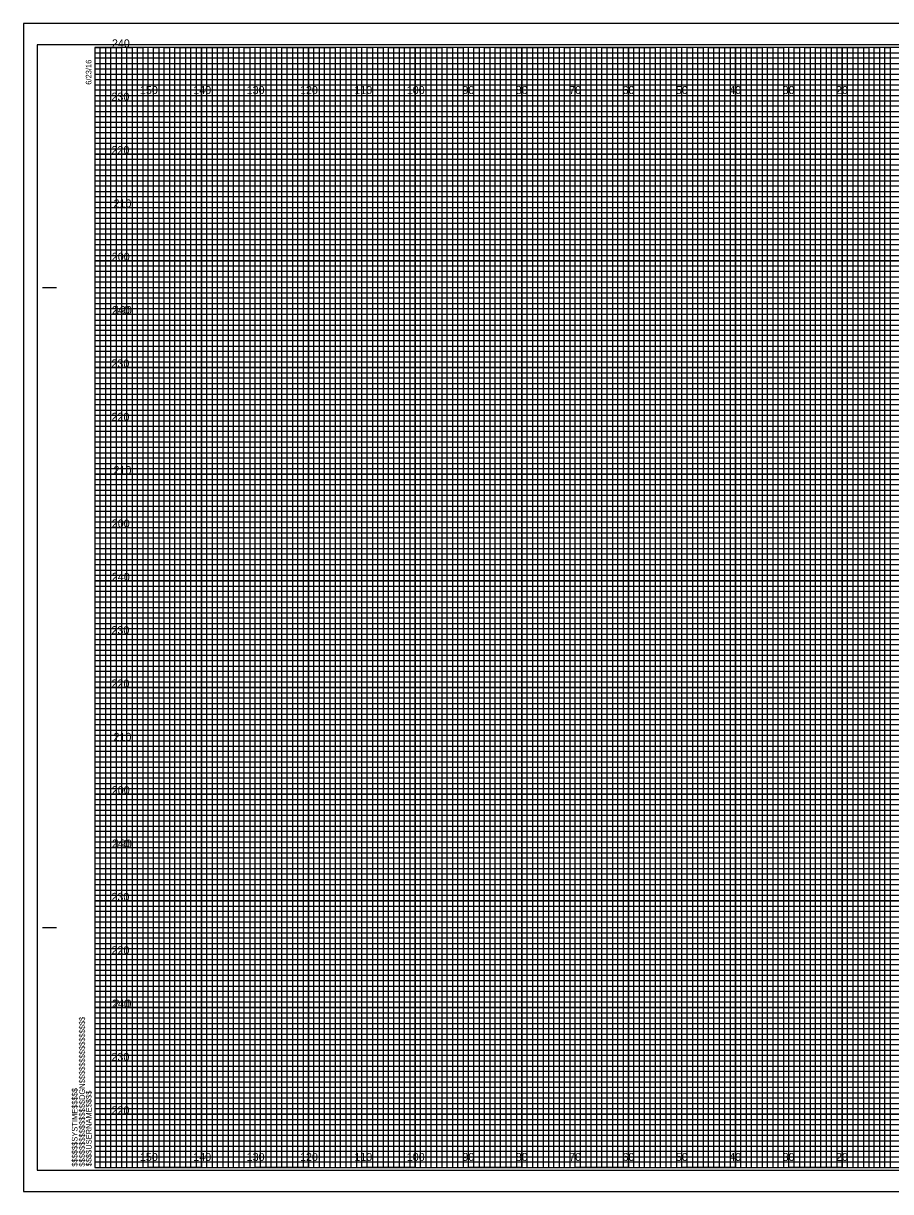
# Model space of a CAD drawing. Extents: x -13 to 359, y -5 to 2854.
# Drawn here: x -13.4 to 149.1, y 1315.5 to 1534.5 of the extents above; entities that cross this region are included whole.
import ezdxf

# ---------------------------------------------------------------- set-up
doc = ezdxf.new("R2010")
doc.units = 0
for name, color, linetype in [('Exist Cross Section Cell', 7, 'Continuous'), ('Exist XS Ground Line', 7, 'Continuous'), ('Prop CMT Concrete Structures', 7, 'Continuous'), ('Prop CMT DNC', 7, 'Continuous'), ('Prop CMT Pvmt Course 1', 7, 'Continuous'), ('Prop CMT Pvmt Course 1 CG', 7, 'Continuous'), ('Prop CMT Pvmt Course 2', 7, 'Continuous'), ('Prop CMT Shear Line', 7, 'Continuous'), ('Prop CMT Slope Grass', 7, 'Continuous'), ('Prop CMT Subgrade Earthwork', 7, 'Continuous'), ('Scratch_Level_0', 7, 'Continuous')]:
    doc.layers.add(name, color=color, linetype=linetype)

msp = doc.modelspace()

# ---------------------------------------------------------------- linework, layer by layer
at = {"layer": 'Exist XS Ground Line'}
for p, q in [((10, 1530), (0, 1530)), ((10, 1320), (10, 1530)), ((30, 1530), (20, 1530)), ((20, 1530), (20, 1320)), ((30, 1320), (30, 1530)), ((50, 1530), (40, 1530)), ((40, 1530), (40, 1320)), ((50, 1320), (50, 1530)), ((70, 1530), (60, 1530)), ((60, 1530), (60, 1320)), ((70, 1320), (70, 1530)), ((90, 1530), (80, 1530)), ((80, 1530), (80, 1320)), ((90, 1320), (90, 1530)), ((110, 1530), (100, 1530)), ((100, 1530), (100, 1320)), ((110, 1320), (110, 1530)), ((130, 1530), (120, 1530)), ((120, 1530), (120, 1320)), ((130, 1320), (130, 1530)), ((150, 1530), (140, 1530)), ((140, 1530), (140, 1320)), ((20, 1320), (10, 1320)), ((40, 1320), (30, 1320)), ((60, 1320), (50, 1320)), ((80, 1320), (70, 1320)), ((100, 1320), (90, 1320)), ((120, 1320), (110, 1320)), ((140, 1320), (130, 1320))]:
    msp.add_line(p, q, dxfattribs=at)
for points in [[(0, 1520), (320, 1520), (320, 1510), (0, 1510)], [(0, 1500), (320, 1500), (320, 1490), (0, 1490)], [(0, 1480), (320, 1480), (320, 1470), (0, 1470)], [(0, 1460), (320, 1460), (320, 1450), (0, 1450)], [(0, 1440), (320, 1440), (320, 1430), (0, 1430)], [(0, 1420), (320, 1420), (320, 1410), (0, 1410)], [(0, 1400), (320, 1400), (320, 1390), (0, 1390)], [(0, 1380), (320, 1380), (320, 1370), (0, 1370)], [(0, 1360), (320, 1360), (320, 1350), (0, 1350)], [(0, 1340), (320, 1340), (320, 1330), (0, 1330)]]:
    msp.add_lwpolyline(points, dxfattribs=at)
at = {"layer": 'Prop CMT Concrete Structures'}
for p, q in [((-9.8, 1485), (-7.3, 1485)), ((-9.7, 1485), (-7.2, 1485)), ((-9.8, 1365), (-7.3, 1365)), ((-9.7, 1365), (-7.2, 1365)), ((0, 1320), (0, 1320)), ((0, 1320), (0, 1320)), ((0, 1320), (0, 1320)), ((0, 1320), (0, 1320)), ((0, 1320), (0, 1320)), ((0, 1320), (0, 1320)), ((0, 1320), (0, 1320))]:
    msp.add_line(p, q, dxfattribs=at)
msp.add_lwpolyline([(320, 1530), (0, 1530), (0, 1320), (320, 1320)], close=True, dxfattribs=at)
at = {"layer": 'Prop CMT DNC'}
for p, q in [((323.3, 1534.5), (-13.4, 1534.5)), ((-13.4, 1534.5), (-13.4, 1315.5)), ((-13.4, 1315.5), (323.3, 1315.5))]:
    msp.add_line(p, q, dxfattribs=at)
at = {"layer": 'Prop CMT Pvmt Course 1'}
for p, q in [((0, 1529), (260, 1529)), ((260, 1527.98), (0, 1527.98)), ((0, 1527.98), (0, 1527)), ((0, 1527), (260, 1527)), ((260, 1525.89), (0, 1525.89)), ((0, 1525.89), (0, 1524)), ((0, 1524), (320, 1524))]:
    msp.add_line(p, q, dxfattribs=at)
for points in [[(0, 1523), (270, 1523), (320, 1523), (320, 1522), (0, 1522)], [(0, 1521), (320, 1521), (320, 1519), (0, 1519)], [(0, 1518), (320, 1518), (320, 1517), (0, 1516.98)], [(0, 1516), (320, 1516), (320, 1514), (0, 1514)], [(0, 1513), (320, 1513), (320, 1512), (0, 1512)], [(0, 1511), (320, 1511), (320, 1509), (0, 1509)], [(0, 1508), (320, 1508), (320, 1507), (0, 1507)], [(0, 1506), (320, 1506), (320, 1504), (0, 1504)], [(0, 1503), (320, 1503), (320, 1502), (0, 1502)], [(0, 1501), (320, 1501), (320, 1499), (0, 1499)], [(0, 1498), (320, 1498), (320, 1497), (0, 1497)], [(0, 1496), (320, 1496), (320, 1493.95), (320, 1493), (320, 1492), (0, 1492)], [(0, 1494), (320, 1494), (320, 1493), (0, 1493)], [(0, 1491), (320, 1491), (320, 1489), (0, 1489.03)], [(0, 1489.03), (320, 1489), (320, 1488), (0, 1488)], [(0, 1487), (320, 1487), (320, 1486), (0, 1486)], [(0, 1484), (320, 1484), (320, 1483), (0, 1483)], [(0, 1482), (320, 1482), (320, 1481), (0, 1481)], [(-0.07, 1478.89), (320, 1478.89), (320, 1477.88), (-0.07, 1477.88)], [(0, 1477), (320, 1477), (320, 1476), (0, 1476)], [(0, 1474), (320, 1474), (320, 1473), (0, 1473)], [(0, 1472), (320, 1472), (320, 1471), (0, 1471)], [(0, 1469), (320, 1469), (320, 1468), (0, 1468)], [(0, 1467), (320, 1467), (320, 1466), (0, 1466)], [(0, 1464), (320, 1464), (320, 1463), (0, 1463)], [(0, 1462), (320, 1462), (320, 1461), (0, 1461)], [(0, 1459), (320, 1459), (319.99, 1457.98), (0, 1458)], [(0, 1457), (320, 1457), (320, 1456), (0, 1456)], [(0, 1454), (320, 1454), (320, 1453), (0, 1453)], [(0, 1452), (320, 1452), (320, 1451), (0, 1451)], [(0, 1449), (320, 1449), (320, 1448), (0, 1448)], [(0, 1447), (320, 1447), (320, 1446), (0, 1446)], [(0, 1444), (320, 1444), (320, 1443), (0, 1443)], [(0, 1442), (320, 1442), (320, 1441), (0, 1441)], [(0, 1439), (320, 1439), (320, 1438), (0, 1438)], [(0, 1436.99), (320.07, 1436.91), (320, 1436), (0, 1436)], [(0, 1434), (320, 1434), (320, 1433), (0, 1433)], [(0, 1432), (320, 1432), (320, 1431), (0, 1431)], [(0, 1429), (320, 1429), (320, 1428), (0, 1428)], [(0, 1427), (320, 1427), (320, 1426), (0, 1426)], [(0, 1424), (320, 1424), (320, 1423), (0, 1423)], [(0, 1422), (320, 1422), (320, 1421), (0, 1421)], [(0, 1419), (320, 1419), (320, 1418), (0, 1418)], [(0, 1417), (320, 1417), (320, 1416), (0, 1416)], [(0, 1414), (320, 1414), (320, 1413), (0, 1413)], [(0, 1412), (320, 1412), (320, 1411), (0, 1411)], [(0, 1409), (320, 1409), (320, 1408), (0, 1408)], [(0, 1407), (320, 1407), (320, 1406), (0, 1406)], [(0, 1404), (320, 1404), (320, 1403), (0, 1403)], [(0, 1402), (320, 1402), (320, 1401), (0, 1401)], [(0, 1399), (320, 1399), (319.99, 1397.98), (0, 1398)], [(0, 1397), (320, 1397), (320, 1396), (0, 1396)], [(0, 1394), (320, 1394), (320, 1393), (0, 1393)], [(0, 1392), (320, 1392), (320, 1391), (0, 1391)], [(0, 1389), (320, 1389), (320, 1388), (0, 1388)], [(0, 1387), (320, 1387), (320, 1386), (0, 1386)], [(0, 1384), (320, 1384), (320, 1383), (0, 1383)], [(0, 1382), (320, 1382), (320, 1381), (0, 1381)], [(0, 1379), (320, 1379), (320, 1378), (0, 1378)], [(0, 1376.99), (320.07, 1376.91), (320, 1376), (0, 1376)], [(0, 1374), (320, 1374), (320, 1373), (0, 1373)], [(0, 1372), (320, 1372), (320, 1371), (0, 1371)], [(0, 1369), (320, 1369), (320, 1368), (0, 1368)], [(0, 1367), (320, 1367), (320, 1366), (0, 1366)], [(0, 1364), (320, 1364), (320, 1363), (0, 1363)], [(0, 1362), (320, 1362), (320, 1361), (0, 1361)], [(0, 1359), (320, 1359), (320, 1358), (0, 1358)], [(0, 1357), (320, 1357), (320, 1356), (0, 1356)], [(0, 1354), (320, 1354), (320, 1353), (0, 1353)], [(0, 1352), (320, 1352), (320, 1351), (0, 1351)], [(0, 1349), (320, 1349), (320, 1348), (0, 1348)], [(0, 1347), (320, 1347), (320, 1346), (0, 1346)], [(0, 1344), (320, 1344), (320, 1343), (0, 1343)], [(0, 1342), (320, 1342), (320, 1341), (0, 1341)], [(0, 1339), (320, 1339), (320, 1338), (0, 1338)], [(0, 1337), (320, 1337), (320, 1336), (0, 1336)], [(0, 1334), (320, 1334), (320, 1333), (0, 1333)], [(0, 1332), (320, 1332), (320, 1331), (0, 1331)], [(0, 1329), (320, 1329), (320, 1328), (0, 1328)], [(0, 1327), (320, 1327), (320, 1326), (0, 1326)], [(0, 1324), (320, 1324), (320, 1323), (0, 1323)], [(0, 1322), (320, 1322), (320, 1321), (0, 1321)]]:
    msp.add_lwpolyline(points, dxfattribs=at)
at = {"layer": 'Prop CMT Pvmt Course 1 CG'}
for points in [[(0, 1320), (1, 1320), (1, 1530), (2, 1530), (2, 1320)], [(2, 1320), (3, 1320), (3, 1530), (4, 1530), (4, 1320)], [(5, 1320), (6, 1320), (6, 1530), (7, 1530), (7, 1320)], [(7, 1320), (8, 1320), (8, 1530), (9, 1530), (9, 1320)], [(10, 1320), (11, 1320), (11, 1530), (12, 1530), (12, 1320)], [(12, 1320), (13, 1320), (13, 1530), (14, 1530), (14, 1320)], [(15, 1320), (16, 1320), (16, 1530), (17, 1530), (17, 1320)], [(17, 1320), (18, 1320), (18, 1530), (19, 1530), (19, 1320)], [(20, 1320), (21, 1320), (21, 1530), (22, 1530), (22, 1320)], [(22, 1320), (23, 1320), (23, 1530), (24, 1530), (24, 1320)], [(25, 1320), (26, 1320), (26, 1530), (27, 1530), (27, 1320)], [(27, 1320), (28, 1320), (28, 1530), (29, 1530), (29, 1320)], [(30, 1320), (31, 1320), (31, 1530), (32, 1530), (32, 1320)], [(32, 1320), (33, 1320), (33, 1530), (34, 1530), (34, 1320)], [(35, 1320), (36, 1320), (36, 1530), (37, 1530), (37, 1320)], [(37, 1320), (38, 1320), (38, 1530), (39, 1530), (39, 1320)], [(40, 1320), (41, 1320), (41, 1530), (42, 1530), (42, 1320)], [(42, 1320), (43, 1320), (43, 1530), (44, 1530), (44, 1320)], [(45, 1320), (46, 1320), (46, 1530), (47, 1530), (47, 1320)], [(47, 1320), (48, 1320), (48, 1530), (49, 1530), (49, 1320)], [(50, 1320), (51, 1320), (51, 1530), (52, 1530), (52, 1320)], [(52, 1320), (53, 1320), (53, 1530), (54, 1530), (54, 1320)], [(55, 1320), (56, 1320), (56, 1530), (57, 1530), (57, 1320)], [(57, 1320), (58, 1320), (58, 1530), (59, 1530), (59, 1320)], [(60, 1320), (61, 1320), (61, 1530), (62, 1530), (62, 1320)], [(62, 1320), (63, 1320), (63, 1530), (64, 1530), (64, 1320)], [(65, 1320), (66, 1320), (66, 1530), (67, 1530), (67, 1320)], [(67, 1320), (68, 1320), (68, 1530), (69, 1530), (69, 1320)], [(70, 1320), (71, 1320), (71, 1530), (72, 1530), (72, 1320)], [(72, 1320), (73, 1320), (73, 1530), (74, 1530), (74, 1320)], [(75, 1320), (76, 1320), (76, 1530), (77, 1530), (77, 1320)], [(77, 1320), (78, 1320), (78, 1530), (79, 1530), (79, 1320)], [(80, 1320), (81, 1320), (81, 1530), (82, 1530), (82, 1320)], [(82, 1320), (83, 1320), (83, 1530), (84, 1530), (84, 1320)], [(85, 1320), (86, 1320), (86, 1530), (87, 1530), (87, 1320)], [(87, 1320), (88, 1320), (88, 1530), (89, 1530), (89, 1320)], [(90, 1320), (91, 1320), (91, 1530), (92, 1530), (92, 1320)], [(92, 1320), (93, 1320), (93, 1530), (94, 1530), (94, 1320)], [(95, 1320), (96, 1320), (96, 1530), (97, 1530), (97, 1320)], [(97, 1320), (98, 1320), (98, 1530), (99, 1530), (99, 1320)], [(100, 1320), (101, 1320), (101, 1530), (102, 1530), (102, 1320)], [(102, 1320), (103, 1320), (103, 1530), (104, 1530), (104, 1320)], [(105, 1320), (106, 1320), (106, 1530), (107, 1530), (107, 1320)], [(107, 1320), (108, 1320), (108, 1530), (109, 1530), (109, 1320)], [(110, 1320), (111, 1320), (111, 1530), (112, 1530), (112, 1320)], [(112, 1320), (113, 1320), (113, 1530), (114, 1530), (114, 1320)], [(115, 1320), (116, 1320), (116, 1530), (117, 1530), (117, 1320)], [(117, 1320), (118, 1320), (118, 1530), (119, 1530), (119, 1320)], [(120, 1320), (121, 1320), (121, 1530), (122, 1530), (122, 1320)], [(122, 1320), (123, 1320), (123, 1530), (124, 1530), (124, 1320)], [(125, 1320), (126, 1320), (126, 1530), (127, 1530), (127, 1320)], [(127, 1320), (128, 1320), (128, 1530), (129, 1530), (129, 1320)], [(130, 1320), (131, 1320), (131, 1530), (132, 1530), (132, 1320)], [(132, 1320), (133, 1320), (133, 1530), (134, 1530), (134, 1320)], [(135, 1320), (136, 1320), (136, 1530), (137, 1530), (137, 1320)], [(137, 1320), (138, 1320), (138, 1530), (139, 1530), (139, 1320)], [(140, 1320), (141, 1320), (141, 1530), (142, 1530), (142, 1320)], [(142, 1320), (143, 1320), (143, 1530), (144, 1530), (144, 1320)], [(145, 1320), (146, 1320), (146, 1530), (147, 1530), (147, 1320)], [(147, 1320), (148, 1320), (148, 1530), (149, 1530), (149, 1320)]]:
    msp.add_lwpolyline(points, dxfattribs=at)
at = {"layer": 'Prop CMT Shear Line'}
for p, q in [((10, 1320), (10, 1530)), ((20, 1320), (20, 1530)), ((30, 1320), (30, 1530)), ((40, 1320), (40, 1530)), ((50, 1320), (50, 1530)), ((60, 1320), (60, 1530)), ((70, 1320), (70, 1530)), ((80, 1320), (80, 1530)), ((90, 1320), (90, 1530)), ((100, 1320), (100, 1530)), ((110, 1320), (110, 1530)), ((120, 1320), (120, 1530)), ((130, 1320), (130, 1530)), ((140, 1320), (140, 1530)), ((0, 1520), (320, 1520)), ((0, 1510), (320, 1510)), ((0, 1500), (320, 1500)), ((0, 1490), (320, 1490)), ((0, 1480), (320, 1480)), ((0, 1470), (320, 1470)), ((0, 1460), (320, 1460)), ((0, 1450), (320, 1450)), ((0, 1440), (320, 1440)), ((0, 1430), (320, 1430)), ((0, 1420), (320, 1420)), ((0, 1410), (320, 1410)), ((0, 1400), (320, 1400)), ((0, 1390), (320, 1390)), ((0, 1380), (320, 1380)), ((0, 1370), (320, 1370)), ((0, 1360), (320, 1360)), ((0, 1350), (320, 1350)), ((0, 1340), (320, 1340)), ((0, 1330), (320, 1330))]:
    msp.add_line(p, q, dxfattribs=at)
at = {"layer": 'Prop CMT Slope Grass'}
msp.add_lwpolyline([(-10.8, 1319.5), (322.4, 1319.5), (322.4, 1530.5), (-10.8, 1530.5)], close=True, dxfattribs=at)
at = {"layer": 'Prop CMT Subgrade Earthwork'}
msp.add_lwpolyline([(-13.4, 1315.5), (323.3, 1315.5), (323.3, 1534.5), (-13.4, 1534.5)], close=True, dxfattribs=at)
at = {"layer": 'Scratch_Level_0'}
for points in [[(0, 1530), (5, 1530), (5, 1320), (15, 1320), (15, 1530), (25, 1530), (25, 1320), (35, 1320), (35, 1530), (45, 1530), (45, 1320), (55, 1320), (55, 1530), (65, 1530), (65, 1320), (75, 1320), (75, 1530), (85, 1530), (85, 1320), (95, 1320), (95, 1530), (105, 1530), (105, 1320), (115, 1320), (115, 1530), (125, 1530), (125, 1320), (135, 1320), (135, 1530), (145, 1530), (145, 1320), (155, 1320)], [(0, 1525), (275, 1525)], [(0, 1505), (320, 1505), (320, 1515), (0, 1515)], [(0, 1485), (320, 1485), (320, 1495), (0, 1495)], [(0, 1465), (320, 1465), (320, 1475), (0, 1475)], [(0, 1445), (320, 1445), (320, 1455), (0, 1455)], [(0, 1425), (320, 1425), (320, 1435), (0, 1435)], [(0, 1405), (320, 1405), (320, 1415), (0, 1415)], [(0, 1385), (320, 1385), (320, 1395), (0, 1395)], [(0, 1365), (320, 1365), (320, 1375), (0, 1375)], [(0, 1345), (320, 1345), (320, 1355), (0, 1355)], [(0, 1325), (320, 1325), (320, 1335), (0, 1335)]]:
    msp.add_lwpolyline(points, dxfattribs=at)

# ---------------------------------------------------------------- texts
at = {"layer": 'Exist Cross Section Cell'}
for s, p in [('150', (8.44, 1521.25)), ('140', (18.44, 1521.25)), ('130', (28.44, 1521.25)), ('120', (38.44, 1521.25)), ('110', (48.62, 1521.25)), ('100', (58.44, 1521.25)), ('90', (68.86, 1521.25)), ('80', (78.86, 1521.25)), ('70', (88.86, 1521.25)), ('60', (98.86, 1521.25)), ('50', (108.86, 1521.25)), ('40', (118.86, 1521.25)), ('30', (128.86, 1521.25)), ('20', (138.86, 1521.25)), ('150', (8.44, 1321.25)), ('140', (18.44, 1321.25)), ('130', (28.44, 1321.25)), ('120', (38.44, 1321.25)), ('110', (48.62, 1321.25)), ('100', (58.44, 1321.25)), ('90', (68.86, 1321.25)), ('80', (78.86, 1321.25)), ('70', (88.86, 1321.25)), ('60', (98.86, 1321.25)), ('50', (108.86, 1321.25)), ('40', (118.86, 1321.25)), ('30', (128.86, 1321.25)), ('20', (138.86, 1321.25))]:
    msp.add_text(s, height=1.5, dxfattribs=at).set_placement(p)
at = {"layer": 'Prop CMT Concrete Structures'}
for s, p in [('6/23/16', (-0.65, 1523)), ('$$$$$$$$$$$$$$$$DGN$$$$$$$$$$$$$$$$', (-1.88, 1320.18)), ('$$$$$$SYSTIME$$$$$', (-3.26, 1320.18)), ('$$$$USERNAME$$$$', (-0.62, 1320.23))]:
    msp.add_text(s, height=1.05, rotation=90, dxfattribs=at).set_placement(p)
at = {"layer": 'Prop CMT Pvmt Course 2'}
for s, p in [('240', (3.19, 1530)), ('230', (3.11, 1520)), ('220', (3.12, 1510)), ('210', (3.5, 1500)), ('200', (3.17, 1490)), ('240', (3.19, 1480)), ('190', (3.57, 1480)), ('230', (3.11, 1470)), ('220', (3.12, 1460)), ('210', (3.5, 1450)), ('200', (3.17, 1440)), ('240', (3.19, 1430)), ('230', (3.11, 1420)), ('220', (3.12, 1410)), ('210', (3.5, 1400)), ('200', (3.17, 1390)), ('240', (3.19, 1380)), ('190', (3.57, 1380)), ('230', (3.11, 1370)), ('220', (3.12, 1360)), ('240', (3.19, 1350)), ('210', (3.5, 1350)), ('230', (3.11, 1340)), ('220', (3.12, 1330))]:
    msp.add_text(s, height=1.5, dxfattribs=at).set_placement(p)

doc.saveas('drawing.dxf')
